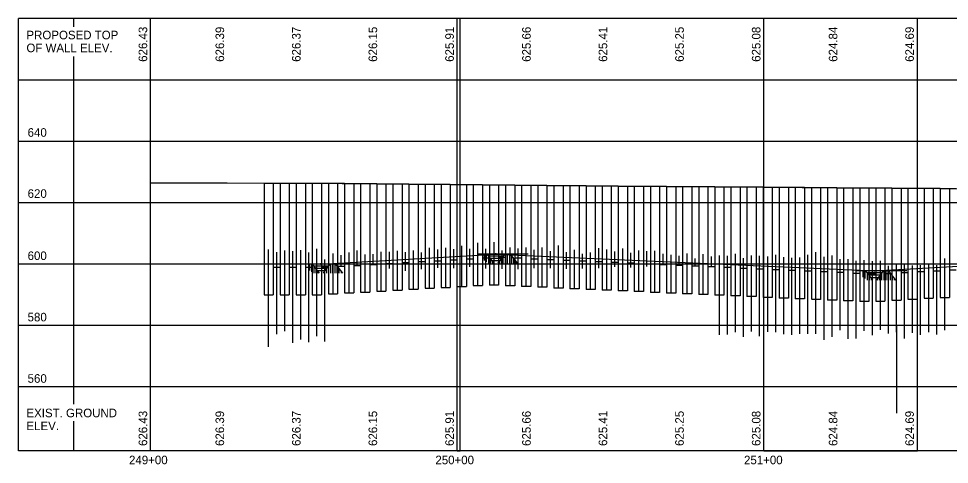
# Model space of a CAD drawing. Extents: x 2267596 to 2268160, y 713755 to 714793.
# Drawn here: x 2267595.7 to 2267899.2, y 713757.9 to 713903.3 of the extents above; entities that cross this region are included whole.
import ezdxf

# ---------------------------------------------------------------- set-up
doc = ezdxf.new("R2010")
doc.units = 0
for name, color, linetype in [('BR_P_Gen_Text', 7, 'Continuous'), ('BR_P_Sub_Deep_Object', 7, 'Continuous'), ('Default', 7, 'Continuous'), ('GE_X_Alignment', 7, 'Continuous'), ('SC_Scratch1', 7, 'Continuous'), ('SC_Scratch3', 7, 'Continuous'), ('SC_Scratch9', 7, 'Continuous'), ('SH_Major_Grid_Line', 7, 'Continuous'), ('XS_X_Ground_Line', 7, 'Continuous')]:
    doc.layers.add(name, color=color, linetype=linetype)

msp = doc.modelspace()

# ---------------------------------------------------------------- linework, layer by layer
at = {"layer": 'BR_P_Sub_Deep_Object'}
for p, q in [((2267675.74, 713849.69), (2267675.74, 713813.21)), ((2267675.74, 713849.69), (2267678.74, 713849.69)), ((2267678.74, 713849.69), (2267678.74, 713813.21)), ((2267678.74, 713849.69), (2267680.99, 713849.69)), ((2267680.99, 713849.69), (2267680.99, 713813.21)), ((2267680.99, 713849.69), (2267683.99, 713849.69)), ((2267683.99, 713849.69), (2267683.99, 713813.21)), ((2267683.99, 713849.69), (2267686.24, 713849.69)), ((2267686.24, 713849.69), (2267689.24, 713849.68)), ((2267686.24, 713849.68), (2267686.24, 713813.21)), ((2267689.24, 713849.68), (2267689.24, 713813.21)), ((2267689.24, 713849.68), (2267691.49, 713849.68)), ((2267691.49, 713849.68), (2267691.49, 713813.22)), ((2267691.49, 713849.66), (2267694.49, 713849.66)), ((2267694.49, 713849.66), (2267694.49, 713813.22)), ((2267694.49, 713849.63), (2267696.74, 713849.63)), ((2267696.74, 713849.63), (2267696.74, 713813.52)), ((2267696.74, 713849.61), (2267699.74, 713849.61)), ((2267699.74, 713849.61), (2267699.74, 713813.52)), ((2267699.74, 713849.59), (2267701.99, 713849.59)), ((2267701.99, 713849.59), (2267701.99, 713813.83)), ((2267701.99, 713849.57), (2267704.99, 713849.57)), ((2267704.99, 713849.57), (2267704.99, 713813.83)), ((2267704.99, 713849.54), (2267707.24, 713849.54)), ((2267707.24, 713849.54), (2267707.24, 713814.13)), ((2267707.24, 713849.52), (2267710.24, 713849.52)), ((2267710.24, 713849.52), (2267710.24, 713814.13)), ((2267710.24, 713849.49), (2267712.49, 713849.49)), ((2267712.49, 713849.49), (2267712.49, 713814.44)), ((2267712.49, 713849.47), (2267715.49, 713849.47)), ((2267715.49, 713849.47), (2267715.49, 713814.44)), ((2267715.49, 713849.45), (2267717.74, 713849.45)), ((2267717.74, 713849.45), (2267717.74, 713814.74)), ((2267717.74, 713849.42), (2267720.74, 713849.42)), ((2267720.74, 713849.42), (2267720.74, 713814.74)), ((2267720.74, 713849.4), (2267722.99, 713849.4)), ((2267722.99, 713849.4), (2267722.99, 713815.04)), ((2267722.99, 713849.37), (2267725.99, 713849.37)), ((2267725.99, 713849.37), (2267725.99, 713815.04)), ((2267725.99, 713849.35), (2267728.24, 713849.35)), ((2267728.24, 713849.35), (2267728.24, 713815.35)), ((2267728.24, 713849.32), (2267731.24, 713849.32)), ((2267731.24, 713849.32), (2267731.24, 713815.35)), ((2267731.24, 713849.3), (2267733.49, 713849.3)), ((2267733.49, 713849.3), (2267733.49, 713815.65)), ((2267733.49, 713849.27), (2267736.49, 713849.27)), ((2267736.49, 713849.27), (2267736.49, 713815.65)), ((2267736.49, 713849.24), (2267738.74, 713849.24)), ((2267738.74, 713815.96), (2267738.74, 713849.24)), ((2267738.74, 713849.22), (2267741.74, 713849.22)), ((2267741.74, 713849.22), (2267741.74, 713815.96)), ((2267741.74, 713849.19), (2267743.99, 713849.19)), ((2267743.99, 713849.19), (2267743.99, 713816.26)), ((2267743.99, 713849.17), (2267746.99, 713849.17)), ((2267746.99, 713849.17), (2267746.99, 713816.26)), ((2267746.99, 713849.14), (2267749.24, 713849.14)), ((2267749.24, 713849.14), (2267749.24, 713816.37)), ((2267749.24, 713849.12), (2267752.24, 713849.12)), ((2267752.24, 713849.12), (2267752.24, 713816.37)), ((2267752.24, 713849.09), (2267754.49, 713849.09)), ((2267754.49, 713849.09), (2267754.49, 713816.14)), ((2267754.49, 713849.07), (2267757.49, 713849.07)), ((2267757.49, 713849.07), (2267757.49, 713816.14)), ((2267757.49, 713849.04), (2267759.74, 713849.04)), ((2267759.74, 713849.04), (2267759.74, 713815.9)), ((2267759.74, 713849.01), (2267762.74, 713849.01)), ((2267762.74, 713849.01), (2267762.74, 713815.9)), ((2267762.74, 713848.98), (2267764.99, 713848.98)), ((2267764.99, 713848.98), (2267764.99, 713815.67)), ((2267764.99, 713848.96), (2267767.99, 713848.96)), ((2267767.99, 713848.96), (2267767.99, 713815.67)), ((2267767.99, 713848.93), (2267770.24, 713848.93)), ((2267770.24, 713848.93), (2267770.24, 713815.44)), ((2267770.24, 713848.91), (2267773.24, 713848.91)), ((2267773.24, 713848.91), (2267773.24, 713815.44)), ((2267773.24, 713848.88), (2267775.49, 713848.88)), ((2267775.49, 713848.88), (2267775.49, 713815.2)), ((2267775.49, 713848.86), (2267778.49, 713848.86)), ((2267778.49, 713848.86), (2267778.49, 713815.2)), ((2267778.49, 713848.83), (2267780.74, 713848.83)), ((2267780.74, 713848.83), (2267780.74, 713814.97)), ((2267780.74, 713848.8), (2267783.74, 713848.8)), ((2267783.74, 713848.8), (2267783.74, 713814.97)), ((2267783.74, 713848.77), (2267785.99, 713848.77)), ((2267785.99, 713848.77), (2267785.99, 713814.73)), ((2267785.99, 713848.75), (2267788.99, 713848.75)), ((2267788.99, 713848.75), (2267788.99, 713814.73)), ((2267788.99, 713848.72), (2267791.24, 713848.72)), ((2267791.24, 713848.72), (2267791.24, 713814.5)), ((2267791.24, 713848.71), (2267794.24, 713848.71)), ((2267794.24, 713848.71), (2267794.24, 713814.5)), ((2267794.24, 713848.69), (2267796.49, 713848.69)), ((2267796.49, 713848.69), (2267796.49, 713814.27)), ((2267796.49, 713848.67), (2267799.49, 713848.67)), ((2267799.49, 713848.67), (2267799.49, 713814.27)), ((2267799.49, 713848.65), (2267801.74, 713848.65)), ((2267801.74, 713848.65), (2267801.74, 713814.03)), ((2267801.74, 713848.64), (2267804.74, 713848.64)), ((2267804.74, 713848.64), (2267804.74, 713814.03)), ((2267804.74, 713848.62), (2267806.99, 713848.62)), ((2267806.99, 713848.62), (2267806.99, 713813.8)), ((2267806.99, 713848.61), (2267809.99, 713848.61)), ((2267809.99, 713848.61), (2267809.99, 713813.8)), ((2267809.99, 713848.59), (2267812.24, 713848.59)), ((2267812.24, 713848.59), (2267812.24, 713813.56)), ((2267812.24, 713848.57), (2267815.24, 713848.57)), ((2267815.24, 713848.57), (2267815.24, 713813.56)), ((2267815.24, 713848.55), (2267817.49, 713848.55)), ((2267817.49, 713848.55), (2267817.49, 713813.33)), ((2267817.49, 713848.54), (2267820.49, 713848.54)), ((2267820.49, 713848.54), (2267820.49, 713813.33)), ((2267820.49, 713848.52), (2267822.74, 713848.52)), ((2267822.74, 713848.52), (2267822.74, 713813.1)), ((2267822.74, 713848.5), (2267825.74, 713848.5)), ((2267825.74, 713848.5), (2267825.74, 713813.1)), ((2267825.74, 713848.48), (2267827.99, 713848.48)), ((2267827.99, 713848.48), (2267827.99, 713812.86)), ((2267827.99, 713848.47), (2267830.99, 713848.47)), ((2267830.99, 713848.47), (2267830.99, 713812.86)), ((2267830.99, 713848.45), (2267833.24, 713848.45)), ((2267833.24, 713848.45), (2267833.24, 713812.63)), ((2267833.24, 713848.43), (2267836.24, 713848.43)), ((2267836.24, 713848.43), (2267836.24, 713812.63)), ((2267836.24, 713848.41), (2267838.49, 713848.41)), ((2267838.49, 713848.41), (2267838.49, 713812.4)), ((2267838.49, 713848.39), (2267841.49, 713848.39)), ((2267841.49, 713848.39), (2267841.49, 713812.4)), ((2267841.49, 713848.37), (2267843.74, 713848.37)), ((2267843.74, 713848.37), (2267843.74, 713812.16)), ((2267843.74, 713848.35), (2267846.74, 713848.35)), ((2267846.74, 713848.35), (2267846.74, 713812.16)), ((2267846.74, 713848.32), (2267848.99, 713848.32)), ((2267848.99, 713848.32), (2267848.99, 713811.93)), ((2267848.99, 713848.29), (2267851.99, 713848.29)), ((2267851.99, 713848.29), (2267851.99, 713811.93)), ((2267851.99, 713848.27), (2267854.24, 713848.27)), ((2267854.24, 713848.27), (2267854.24, 713811.93)), ((2267854.24, 713848.24), (2267857.24, 713848.24)), ((2267857.24, 713848.24), (2267857.24, 713811.69)), ((2267857.24, 713848.22), (2267859.49, 713848.22)), ((2267859.49, 713848.22), (2267859.49, 713811.46)), ((2267859.49, 713848.19), (2267862.49, 713848.19)), ((2267862.49, 713848.19), (2267862.49, 713811.46)), ((2267862.49, 713848.17), (2267864.74, 713848.17)), ((2267864.74, 713848.17), (2267864.74, 713811.23)), ((2267864.74, 713848.15), (2267867.74, 713848.15)), ((2267867.74, 713848.15), (2267867.74, 713811.23)), ((2267867.74, 713848.13), (2267869.99, 713848.13)), ((2267869.99, 713848.13), (2267869.99, 713811.04)), ((2267869.99, 713848.12), (2267872.99, 713848.12)), ((2267872.99, 713848.12), (2267872.99, 713811.04)), ((2267872.99, 713848.1), (2267875.24, 713848.1)), ((2267875.24, 713848.1), (2267875.24, 713811.21)), ((2267875.24, 713848.08), (2267878.24, 713848.08)), ((2267878.24, 713848.08), (2267878.24, 713811.21)), ((2267878.24, 713848.07), (2267880.49, 713848.07)), ((2267880.49, 713848.07), (2267880.49, 713811.5)), ((2267880.49, 713848.05), (2267883.49, 713848.05)), ((2267883.49, 713848.05), (2267883.49, 713811.5)), ((2267883.49, 713848.03), (2267885.74, 713848.03)), ((2267885.74, 713848.03), (2267885.74, 713811.8)), ((2267885.74, 713848.02), (2267888.74, 713848.02)), ((2267888.74, 713848.02), (2267888.74, 713811.8)), ((2267888.74, 713848), (2267890.99, 713848)), ((2267890.99, 713848), (2267890.99, 713812.09)), ((2267890.99, 713847.99), (2267893.99, 713847.99)), ((2267893.99, 713847.99), (2267893.99, 713812.09)), ((2267893.99, 713847.97), (2267896.24, 713847.97)), ((2267896.24, 713847.97), (2267896.24, 713812.39)), ((2267896.24, 713847.95), (2267899.24, 713847.95)), ((2267899.24, 713847.95), (2267899.24, 713812.39)), ((2267899.24, 713847.93), (2267901.49, 713847.93)), ((2267715.49, 713823.44), (2267717.74, 713823.44)), ((2267720.74, 713823.74), (2267722.99, 713823.74)), ((2267725.99, 713824.04), (2267728.24, 713824.04)), ((2267731.24, 713824.35), (2267733.49, 713824.35)), ((2267736.49, 713824.65), (2267738.74, 713824.65)), ((2267741.74, 713824.96), (2267743.99, 713824.96)), ((2267746.99, 713825.26), (2267749.24, 713825.26)), ((2267754.49, 713825.37), (2267752.24, 713825.37)), ((2267759.74, 713825.14), (2267757.49, 713825.14)), ((2267764.99, 713824.9), (2267762.74, 713824.9)), ((2267770.24, 713824.67), (2267767.99, 713824.67)), ((2267775.49, 713824.44), (2267773.24, 713824.44)), ((2267780.74, 713824.2), (2267778.49, 713824.2)), ((2267785.99, 713823.97), (2267783.74, 713823.97)), ((2267791.24, 713823.73), (2267788.99, 713823.73)), ((2267796.49, 713823.5), (2267794.24, 713823.5)), ((2267678.74, 713822.21), (2267680.99, 713822.21)), ((2267683.99, 713822.21), (2267686.24, 713822.21)), ((2267689.24, 713822.21), (2267691.49, 713822.21)), ((2267694.49, 713822.22), (2267696.74, 713822.22)), ((2267699.74, 713822.52), (2267701.99, 713822.52)), ((2267704.99, 713822.83), (2267707.24, 713822.83)), ((2267710.24, 713823.13), (2267712.49, 713823.13)), ((2267801.74, 713823.27), (2267799.49, 713823.27)), ((2267806.99, 713823.03), (2267804.74, 713823.03)), ((2267812.24, 713822.8), (2267809.99, 713822.8)), ((2267817.49, 713822.56), (2267815.24, 713822.56)), ((2267822.74, 713822.33), (2267820.49, 713822.33)), ((2267827.99, 713822.1), (2267825.74, 713822.1)), ((2267833.24, 713821.86), (2267830.99, 713821.86)), ((2267838.49, 713821.63), (2267836.24, 713821.63)), ((2267843.74, 713821.4), (2267841.49, 713821.4)), ((2267848.99, 713821.16), (2267846.74, 713821.16)), ((2267854.24, 713820.93), (2267851.99, 713820.93)), ((2267859.49, 713820.69), (2267857.24, 713820.69)), ((2267864.74, 713820.46), (2267862.49, 713820.46)), ((2267883.49, 713820.5), (2267885.74, 713820.5)), ((2267888.74, 713820.8), (2267890.99, 713820.8)), ((2267893.99, 713821.09), (2267896.24, 713821.09)), ((2267899.24, 713821.39), (2267901.49, 713821.39)), ((2267869.99, 713820.23), (2267867.74, 713820.23)), ((2267875.24, 713820.04), (2267872.99, 713820.04)), ((2267878.24, 713820.21), (2267880.49, 713820.21)), ((2267712.49, 713814.44), (2267715.49, 713814.44)), ((2267717.74, 713814.74), (2267720.74, 713814.74)), ((2267722.99, 713815.04), (2267725.99, 713815.04)), ((2267728.24, 713815.35), (2267731.24, 713815.35)), ((2267733.49, 713815.65), (2267736.49, 713815.65)), ((2267738.74, 713815.96), (2267741.74, 713815.96)), ((2267743.99, 713816.26), (2267746.99, 713816.26)), ((2267752.24, 713816.37), (2267749.24, 713816.37)), ((2267757.49, 713816.14), (2267754.49, 713816.14)), ((2267762.74, 713815.9), (2267759.74, 713815.9)), ((2267767.99, 713815.67), (2267764.99, 713815.67)), ((2267773.24, 713815.44), (2267770.24, 713815.44)), ((2267778.49, 713815.2), (2267775.49, 713815.2)), ((2267783.74, 713814.97), (2267780.74, 713814.97)), ((2267788.99, 713814.73), (2267785.99, 713814.73)), ((2267794.24, 713814.5), (2267791.24, 713814.5)), ((2267799.49, 713814.27), (2267796.49, 713814.27)), ((2267675.74, 713813.21), (2267678.74, 713813.21)), ((2267680.99, 713813.21), (2267683.99, 713813.21)), ((2267686.24, 713813.21), (2267689.24, 713813.21)), ((2267691.49, 713813.22), (2267694.49, 713813.22)), ((2267696.74, 713813.52), (2267699.74, 713813.52)), ((2267701.99, 713813.83), (2267704.99, 713813.83)), ((2267707.24, 713814.13), (2267710.24, 713814.13)), ((2267804.74, 713814.03), (2267801.74, 713814.03)), ((2267809.99, 713813.8), (2267806.99, 713813.8)), ((2267815.24, 713813.56), (2267812.24, 713813.56)), ((2267820.49, 713813.33), (2267817.49, 713813.33)), ((2267825.74, 713813.1), (2267822.74, 713813.1)), ((2267830.99, 713812.86), (2267827.99, 713812.86)), ((2267836.24, 713812.63), (2267833.24, 713812.63)), ((2267841.49, 713812.4), (2267838.49, 713812.4)), ((2267846.74, 713812.16), (2267843.74, 713812.16)), ((2267851.99, 713811.93), (2267848.99, 713811.93)), ((2267857.24, 713811.69), (2267854.24, 713811.69)), ((2267862.49, 713811.46), (2267859.49, 713811.46)), ((2267867.74, 713811.23), (2267864.74, 713811.23)), ((2267880.49, 713811.5), (2267883.49, 713811.5)), ((2267885.74, 713811.8), (2267888.74, 713811.8)), ((2267890.99, 713812.09), (2267893.99, 713812.09)), ((2267896.24, 713812.39), (2267899.24, 713812.39)), ((2267872.99, 713811.04), (2267869.99, 713811.04)), ((2267875.24, 713811.21), (2267878.24, 713811.21))]:
    msp.add_line(p, q, dxfattribs=at)
at = {"layer": 'Default'}
for p, q in [((2267761.9, 713826.51), (2267745.5, 713826.51)), ((2267747.52, 713826.51), (2267747.52, 713824.45)), ((2267748.21, 713826.51), (2267748.21, 713824.02)), ((2267748.43, 713826.51), (2267750.7, 713823.56)), ((2267754.14, 713826.51), (2267752, 713823.56)), ((2267754.36, 713826.51), (2267754.36, 713823.56)), ((2267755.05, 713826.51), (2267755.05, 713823.56)), ((2267755.75, 713826.51), (2267755.75, 713823.56)), ((2267755.96, 713826.51), (2267758.24, 713823.56)), ((2267748.9, 713825.9), (2267748.9, 713823.56)), ((2267753.67, 713825.87), (2267748.9, 713825.87)), ((2267753.12, 713825.11), (2267749.51, 713825.11)), ((2267749.59, 713825), (2267749.59, 713823.56)), ((2267752.55, 713824.32), (2267750.11, 713824.32)), ((2267750.27, 713824.12), (2267750.27, 713823.56)), ((2267752.37, 713824.07), (2267752.37, 713823.56)), ((2267753.02, 713824.97), (2267753.02, 713823.56)), ((2267753.67, 713825.87), (2267753.67, 713823.56)), ((2267756.44, 713825.9), (2267756.44, 713823.56)), ((2267757.13, 713825), (2267757.13, 713823.56)), ((2267757.81, 713824.12), (2267757.81, 713823.56)), ((2267704.94, 713823.21), (2267688.55, 713823.21)), ((2267690.56, 713823.21), (2267690.56, 713821.15)), ((2267691.26, 713823.21), (2267691.26, 713820.72)), ((2267691.47, 713823.21), (2267693.75, 713820.26)), ((2267691.95, 713822.6), (2267691.95, 713820.26)), ((2267696.72, 713822.57), (2267691.95, 713822.57)), ((2267696.17, 713821.81), (2267692.55, 713821.81)), ((2267692.64, 713821.7), (2267692.64, 713820.26)), ((2267695.6, 713821.02), (2267693.16, 713821.02)), ((2267693.32, 713820.82), (2267693.32, 713820.26)), ((2267697.18, 713823.21), (2267695.05, 713820.26)), ((2267695.41, 713820.77), (2267695.41, 713820.26)), ((2267696.07, 713821.67), (2267696.07, 713820.26)), ((2267696.72, 713822.57), (2267696.72, 713820.26)), ((2267697.41, 713823.21), (2267697.41, 713820.26)), ((2267698.1, 713823.21), (2267698.1, 713820.26)), ((2267698.79, 713823.21), (2267698.79, 713820.26)), ((2267699.01, 713823.21), (2267701.29, 713820.26)), ((2267699.48, 713822.6), (2267699.48, 713820.26)), ((2267700.17, 713821.7), (2267700.17, 713820.26)), ((2267700.86, 713820.82), (2267700.86, 713820.26)), ((2267885.37, 713821.01), (2267868.98, 713821.01)), ((2267870.99, 713821.01), (2267870.99, 713818.95)), ((2267871.68, 713821.01), (2267871.68, 713818.52)), ((2267871.9, 713821.01), (2267874.18, 713818.06)), ((2267872.38, 713820.4), (2267872.38, 713818.06)), ((2267877.15, 713820.37), (2267872.38, 713820.37)), ((2267877.61, 713821.01), (2267875.48, 713818.06)), ((2267877.15, 713820.37), (2267877.15, 713818.06)), ((2267877.84, 713821.01), (2267877.84, 713818.06)), ((2267878.53, 713821.01), (2267878.53, 713818.06)), ((2267879.22, 713821.01), (2267879.22, 713818.06)), ((2267879.44, 713821.01), (2267881.72, 713818.06)), ((2267879.91, 713820.4), (2267879.91, 713818.06)), ((2267876.6, 713819.61), (2267872.98, 713819.61)), ((2267873.07, 713819.5), (2267873.07, 713818.06)), ((2267876.03, 713818.82), (2267873.59, 713818.82)), ((2267873.75, 713818.62), (2267873.75, 713818.06)), ((2267875.84, 713818.57), (2267875.84, 713818.06)), ((2267876.5, 713819.47), (2267876.5, 713818.06)), ((2267880.6, 713819.5), (2267880.6, 713818.06)), ((2267881.29, 713818.62), (2267881.29, 713818.06))]:
    msp.add_line(p, q, dxfattribs=at)
at = {"layer": 'GE_X_Alignment'}
for p, q in [((2267613.74, 713900.65), (2267613.74, 713903.31)), ((2267638.74, 713762.33), (2267638.74, 713903.31)), ((2267738.74, 713762.33), (2267738.74, 713903.31)), ((2267838.74, 713762.33), (2267838.74, 713903.31)), ((2267613.74, 713777.52), (2267613.74, 713891.01)), ((2267595.7, 713883.31), (2268156.77, 713883.31)), ((2267595.7, 713863.31), (2268156.77, 713863.31)), ((2267595.7, 713843.31), (2268156.77, 713843.31)), ((2267595.7, 713823.31), (2268156.77, 713823.31)), ((2267595.7, 713803.31), (2268156.77, 713803.31)), ((2267595.7, 713783.31), (2268156.77, 713783.31)), ((2267613.74, 713762.33), (2267613.74, 713772.01))]:
    msp.add_line(p, q, dxfattribs=at)
at = {"layer": 'SC_Scratch1'}
for p, q in [((2267745.49, 713816.26), (2267745.49, 713830.17)), ((2267750.74, 713816.37), (2267750.74, 713830.4)), ((2267677.24, 713796.26), (2267677.24, 713827.96)), ((2267679.87, 713800.39), (2267679.87, 713827.17)), ((2267682.49, 713801.33), (2267682.49, 713827.64)), ((2267685.12, 713797.54), (2267685.12, 713827.49)), ((2267687.74, 713798.63), (2267687.74, 713827.8)), ((2267690.37, 713797.75), (2267690.37, 713827.06)), ((2267692.99, 713799.78), (2267692.99, 713828.27)), ((2267698.24, 713813.52), (2267698.24, 713826.72)), ((2267703.49, 713813.83), (2267703.49, 713827.05)), ((2267706.12, 713822.83), (2267706.12, 713827.71)), ((2267711.37, 713823.13), (2267711.37, 713826.44)), ((2267713.99, 713814.44), (2267713.99, 713827.22)), ((2267716.62, 713821.77), (2267716.62, 713827.22)), ((2267719.24, 713814.74), (2267719.24, 713827.59)), ((2267721.87, 713821.07), (2267721.87, 713827.17)), ((2267724.49, 713815.04), (2267724.49, 713827.64)), ((2267727.12, 713821.63), (2267727.12, 713827.07)), ((2267729.74, 713815.35), (2267729.74, 713828.53)), ((2267732.37, 713822.05), (2267732.37, 713827.96)), ((2267734.99, 713815.65), (2267734.99, 713828.58)), ((2267737.62, 713821.96), (2267737.62, 713828.11)), ((2267740.24, 713815.96), (2267740.24, 713829.16)), ((2267742.87, 713822.38), (2267742.87, 713828.22)), ((2267748.12, 713821.83), (2267748.12, 713828.21)), ((2267753.37, 713821.65), (2267753.37, 713827.72)), ((2267755.99, 713816.14), (2267755.99, 713828.68)), ((2267758.62, 713821.59), (2267758.62, 713828.35)), ((2267761.24, 713815.9), (2267761.24, 713828.65)), ((2267763.87, 713821.92), (2267763.87, 713827.89)), ((2267766.49, 713815.67), (2267766.49, 713828.62)), ((2267769.12, 713821.92), (2267769.12, 713827.41)), ((2267771.74, 713815.44), (2267771.74, 713829.35)), ((2267774.37, 713821.72), (2267774.37, 713827.15)), ((2267776.99, 713815.2), (2267776.99, 713827.89)), ((2267779.62, 713821.83), (2267779.62, 713826.58)), ((2267782.24, 713814.97), (2267782.24, 713827.03)), ((2267784.87, 713821.95), (2267784.87, 713828.45)), ((2267787.49, 713814.73), (2267787.49, 713828.03)), ((2267790.12, 713822.31), (2267790.12, 713827.4)), ((2267792.74, 713814.5), (2267792.74, 713828.34)), ((2267795.37, 713822.15), (2267795.37, 713826.88)), ((2267797.99, 713814.27), (2267797.99, 713827.72)), ((2267800.62, 713822.41), (2267800.62, 713827.47)), ((2267803.24, 713814.03), (2267803.24, 713827.56)), ((2267805.87, 713823.03), (2267805.87, 713826.6)), ((2267813.74, 713813.56), (2267813.74, 713826.72)), ((2267818.99, 713813.33), (2267818.99, 713826.52)), ((2267829.49, 713801.05), (2267829.49, 713826.57)), ((2267855.74, 713800.49), (2267855.74, 713827.11)), ((2267695.62, 713797.97), (2267695.62, 713824.76)), ((2267700.87, 713822.52), (2267700.87, 713826.21)), ((2267708.74, 713814.13), (2267708.74, 713826.33)), ((2267808.49, 713813.8), (2267808.49, 713826.28)), ((2267811.12, 713822.8), (2267811.12, 713825.95)), ((2267816.37, 713822.56), (2267816.37, 713825.02)), ((2267821.62, 713822.33), (2267821.62, 713825.74)), ((2267824.24, 713800.14), (2267824.24, 713826.05)), ((2267826.87, 713800.32), (2267826.87, 713825.89)), ((2267832.12, 713799.56), (2267832.12, 713825.21)), ((2267834.74, 713801.3), (2267834.74, 713826.1)), ((2267837.37, 713799.74), (2267837.37, 713825.94)), ((2267839.99, 713801.12), (2267839.99, 713825.74)), ((2267842.62, 713801.06), (2267842.62, 713826.3)), ((2267845.24, 713800.42), (2267845.24, 713825.52)), ((2267847.87, 713800.17), (2267847.87, 713825.25)), ((2267850.49, 713800.45), (2267850.49, 713825.37)), ((2267853.12, 713800.49), (2267853.12, 713826.29)), ((2267858.37, 713798.57), (2267858.37, 713825.65)), ((2267860.99, 713799.53), (2267860.99, 713826.1)), ((2267863.62, 713801.67), (2267863.62, 713824.89)), ((2267866.24, 713798.89), (2267866.24, 713824.86)), ((2267868.87, 713798.99), (2267868.87, 713824.32)), ((2267871.49, 713801.5), (2267871.49, 713824.53)), ((2267874.12, 713800.1), (2267874.12, 713824.23)), ((2267876.74, 713801.84), (2267876.74, 713824.29)), ((2267897.74, 713801.66), (2267897.74, 713825.11)), ((2267879.37, 713800.66), (2267879.37, 713822.66)), ((2267881.99, 713801.03), (2267881.99, 713823.23)), ((2267884.62, 713799), (2267884.62, 713823.02)), ((2267887.24, 713800.84), (2267887.24, 713822.75)), ((2267889.87, 713800.14), (2267889.87, 713822.9)), ((2267892.49, 713801.07), (2267892.49, 713823.11)), ((2267895.12, 713800.28), (2267895.12, 713822.87)), ((2267881.99, 713803.31), (2267881.99, 713774.58))]:
    msp.add_line(p, q, dxfattribs=at)
at = {"layer": 'SC_Scratch3'}
for p, q in [((2267739.65, 713762.33), (2267739.65, 713903.31)), ((2267888.86, 713762.33), (2267888.86, 713903.31)), ((2267738.74, 713762.33), (2267739.65, 713762.33)), ((2267838.74, 713762.33), (2267888.86, 713762.33))]:
    msp.add_line(p, q, dxfattribs=at)
at = {"layer": 'SC_Scratch9'}
for p, q in [((2267751.31, 713826.29), (2267751.31, 713826.82)), ((2267694.36, 713822.99), (2267694.36, 713823.52)), ((2267874.79, 713820.79), (2267874.79, 713821.32))]:
    msp.add_line(p, q, dxfattribs=at)
at = {"layer": 'SH_Major_Grid_Line'}
for p, q in [((2267595.7, 713762.33), (2267595.7, 713903.31)), ((2268156.77, 713903.31), (2267595.7, 713903.31)), ((2268156.77, 713762.33), (2267595.7, 713762.33))]:
    msp.add_line(p, q, dxfattribs=at)
at = {"layer": 'XS_X_Ground_Line'}
msp.add_line((2267694.36, 713823.21), (2267671.93, 713823.21), dxfattribs=at)
for points in [[(2267638.74, 713849.74), (2267663.74, 713849.7), (2267688.74, 713849.68), (2267713.74, 713849.46), (2267738.74, 713849.22), (2267788.74, 713848.72), (2267813.74, 713848.56), (2267838.74, 713848.39), (2267863.74, 713848.15), (2267888.74, 713848), (2267913.74, 713847.83), (2267938.74, 713847.63), (2267963.74, 713847.69), (2267988.74, 713847.62), (2268013.74, 713847.41), (2268049.99, 713847.18)], [(2267694.36, 713823.21), (2267751.31, 713826.51), (2267874.79, 713821.01), (2267952.95, 713825.41), (2268025.6, 713821.91)]]:
    msp.add_lwpolyline(points, dxfattribs=at)

# ---------------------------------------------------------------- texts
at = {"layer": 'BR_P_Gen_Text'}
for s, p in [('PROPOSED TOP ', (2267598.26, 713896.56)), ('OF WALL ELEV.', (2267598.26, 713892.36)), ('640', (2267598.64, 713864.78)), ('620', (2267598.64, 713844.85)), ('600', (2267598.64, 713824.58)), ('580', (2267598.64, 713804.56)), ('560', (2267598.64, 713784.54)), ('EXIST. GROUND', (2267598.26, 713773.29)), ('ELEV.', (2267598.26, 713769.09)), ('249+00', (2267631.71, 713757.96)), ('250+00', (2267731.62, 713757.96)), ('251+00', (2267832.27, 713757.96))]:
    msp.add_text(s, height=2.8, dxfattribs=at).set_placement(p)
for s, p in [('626.43', (2267637.64, 713889.22)), ('626.39', (2267662.72, 713889.22)), ('626.37', (2267687.66, 713889.22)), ('626.15', (2267712.63, 713889.22)), ('625.91', (2267737.64, 713889.22)), ('625.66', (2267762.72, 713889.22)), ('625.41', (2267787.66, 713889.22)), ('625.25', (2267812.63, 713889.22)), ('625.08', (2267837.64, 713889.22)), ('624.84', (2267862.72, 713889.22)), ('624.69', (2267887.66, 713889.22)), ('626.43', (2267637.64, 713763.93)), ('626.39', (2267662.72, 713763.93)), ('626.37', (2267687.66, 713763.93)), ('626.15', (2267712.63, 713763.93)), ('625.91', (2267737.64, 713763.93)), ('625.66', (2267762.72, 713763.93)), ('625.41', (2267787.66, 713763.93)), ('625.25', (2267812.63, 713763.93)), ('625.08', (2267837.64, 713763.93)), ('624.84', (2267862.72, 713763.93)), ('624.69', (2267887.66, 713763.93))]:
    msp.add_text(s, height=2.8, rotation=90, dxfattribs=at).set_placement(p)

doc.saveas('drawing.dxf')
